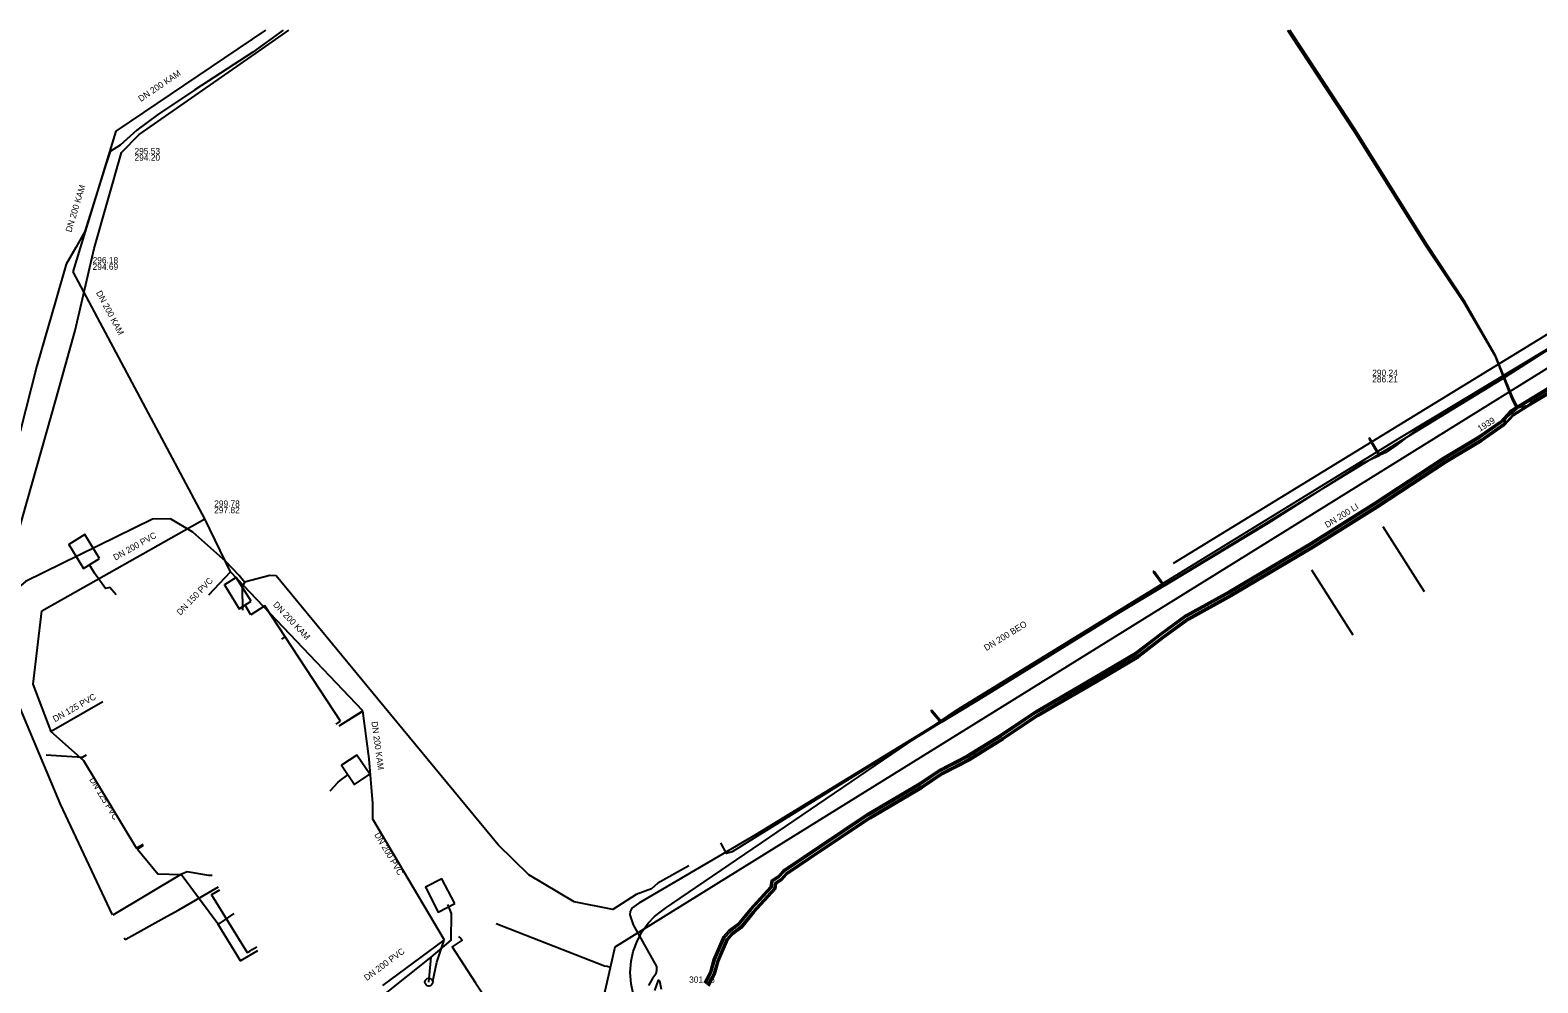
# Model space of a CAD drawing. Extents: x -600391 to -599491, y -1160176 to -1159402.
# Drawn here: x -599833.6 to -599641, y -1159523.5 to -1159401.8 of the extents above; entities that cross this region are included whole.
import ezdxf

# ---------------------------------------------------------------- set-up
doc = ezdxf.new("R2010")
doc.units = 0
for name, color, linetype in [('CETIN_linie', 7, 'Continuous'), ('FASTER_linie', 7, 'Continuous'), ('Vrstva 1', 7, 'Continuous'), ('Vrstva 12', 7, 'Continuous'), ('Vrstva 13', 7, 'Continuous'), ('Vrstva 15', 7, 'Continuous'), ('Vrstva 16', 7, 'Continuous'), ('Vrstva 3', 7, 'Continuous'), ('Vrstva 4', 7, 'Continuous'), ('Vrstva 42', 7, 'Continuous'), ('Vrstva 44', 7, 'Continuous'), ('Vrstva 5', 7, 'Continuous'), ('Vrstva 55', 7, 'Continuous'), ('Vrstva 58', 7, 'Continuous'), ('Vrstva 8', 7, 'Continuous'), ('Vrstva 9', 7, 'Continuous')]:
    doc.layers.add(name, color=color, linetype=linetype)

msp = doc.modelspace()

# ---------------------------------------------------------------- linework, layer by layer
at = {"layer": 'CETIN_linie'}
for points in [[(-599687.5, -1159469.87), (-599639.61, -1159440.54)], [(-599660.76, -1159465.2), (-599655.49, -1159473.49)], [(-599669.88, -1159470.73), (-599664.61, -1159479.02)]]:
    msp.add_lwpolyline(points, dxfattribs=at)
at = {"layer": 'FASTER_linie'}
for points in [[(-599806.85, -1159471.45), (-599808.57, -1159469.66), (-599812.78, -1159465.92), (-599815.61, -1159464.23), (-599817.92, -1159464.25), (-599834.16, -1159472.24), (-599835.99, -1159473.78), (-599837.27, -1159479.34), (-599839.09, -1159485.23)], [(-599806.16, -1159472.29), (-599806.85, -1159471.45)], [(-599806.16, -1159472.29), (-599806.47, -1159472.94), (-599806.42, -1159475.89)], [(-599749.42, -1159508.58), (-599753.39, -1159510.79), (-599754.19, -1159511.5), (-599756.16, -1159512.22), (-599759.12, -1159514.12), (-599764.08, -1159513.14), (-599769.86, -1159509.7), (-599773.76, -1159505.86), (-599789.14, -1159487.25), (-599802.11, -1159471.49), (-599802.92, -1159471.46), (-599806.16, -1159472.29)]]:
    msp.add_lwpolyline(points, dxfattribs=at)
at = {"layer": 'Vrstva 1'}
for p, q in [((-599825.34, -1159471.15), (-599825.96, -1159470.09)), ((-599805.38, -1159476.47), (-599806.08, -1159475.23)), ((-599801.41, -1159479.6), (-599800.97, -1159479.31)), ((-599829.66, -1159500.68), (-599835.73, -1159486.27)), ((-599794.45, -1159490.47), (-599793.92, -1159490.07)), ((-599793.95, -1159497.66), (-599792.96, -1159496.93)), ((-599823.03, -1159514.83), (-599829.66, -1159500.68)), ((-599814.3, -1159509.65), (-599823.01, -1159514.88)), ((-599809.6, -1159515.98), (-599814.26, -1159509.66)), ((-599779.72, -1159514.64), (-599780.21, -1159513.48)), ((-599782.63, -1159523.42), (-599782.34, -1159520.25))]:
    msp.add_line(p, q, dxfattribs=at)
for points in [[(-599658.59, -1159453.85), (-599624.47, -1159433.28), (-599582.91, -1159406.12), (-599577.31, -1159401.77)], [(-599756.17, -1159526.09), (-599756.54, -1159524.86), (-599756.77, -1159523.63), (-599756.9, -1159522.21), (-599756.8, -1159520.76), (-599756.51, -1159519.5), (-599755.99, -1159518.12), (-599755.38, -1159516.95), (-599754.61, -1159515.89), (-599753.8, -1159515.05), (-599752.93, -1159514.34), (-599752.22, -1159513.83), (-599751.58, -1159513.4), (-599715.24, -1159488.66), (-599658.59, -1159453.85)], [(-599822.58, -1159473.92), (-599823.39, -1159472.99), (-599823.91, -1159473.14), (-599825.34, -1159471.15)], [(-599793.92, -1159490.07), (-599800.97, -1159479.31), (-599803.56, -1159475.35), (-599805.38, -1159476.47)], [(-599826.42, -1159494.42), (-599826.9, -1159494.72), (-599831.53, -1159494.41)], [(-599795.25, -1159498.97), (-599794.27, -1159497.91), (-599793.95, -1159497.66)], [(-599819.1, -1159505.98), (-599819.86, -1159506.45), (-599817.23, -1159509.58), (-599814.3, -1159509.65)], [(-599810.3, -1159509.79), (-599810.72, -1159509.79), (-599813.52, -1159509.34), (-599814.3, -1159509.65)], [(-599807.55, -1159514.65), (-599809.44, -1159515.98), (-599809.6, -1159515.98)], [(-599788.42, -1159525.07), (-599782.34, -1159520.25), (-599779.79, -1159518.07), (-599779.72, -1159514.64)], [(-599804.52, -1159519.41), (-599806.67, -1159520.7), (-599809.6, -1159515.98)]]:
    msp.add_lwpolyline(points, dxfattribs=at)
at = {"layer": 'Vrstva 13'}
for points in [[(-599757.93, -1159531.49), (-599760.55, -1159526.41), (-599759.42, -1159521.54), (-599758.81, -1159518.92), (-599742.22, -1159508.61), (-599680.74, -1159470.43), (-599612.05, -1159427.77), (-599574.38, -1159404.36), (-599573.73, -1159403.97), (-599570.13, -1159401.77)], [(-599759.42, -1159521.54), (-599759.85, -1159521.44), (-599760.19, -1159521.36), (-599774.01, -1159515.97)], [(-599778.86, -1159517.59), (-599778.55, -1159517.83), (-599778.39, -1159518.06), (-599779.66, -1159518.93), (-599776.67, -1159523.51), (-599774.59, -1159526.64), (-599774.33, -1159527.11), (-599774.71, -1159529.11), (-599779.55, -1159532.55), (-599783.41, -1159534.94), (-599785.07, -1159534.35), (-599786.65, -1159535.02)]]:
    msp.add_lwpolyline(points, dxfattribs=at)
at = {"layer": 'Vrstva 16'}
for points in [[(-599821.54, -1159517.75), (-599821.41, -1159517.95), (-599821.33, -1159517.91), (-599816.06, -1159515), (-599814.55, -1159514.18), (-599809.51, -1159511.25)], [(-599809.36, -1159511.66), (-599810.4, -1159512.28), (-599805.85, -1159519.63), (-599805.5, -1159519.46), (-599805.19, -1159519.27), (-599804.58, -1159518.91)]]:
    msp.add_lwpolyline(points, dxfattribs=at)
at = {"layer": 'Vrstva 3'}
for points in [[(-599824.69, -1159469.3), (-599826.59, -1159466.24), (-599828.63, -1159467.51), (-599826.73, -1159470.56)], [(-599805.32, -1159474.75), (-599807.23, -1159471.7), (-599808.75, -1159472.66), (-599806.84, -1159475.71)], [(-599790.18, -1159496.86), (-599791.82, -1159494.4), (-599793.79, -1159495.7), (-599792.14, -1159498.15)], [(-599779.32, -1159513.37), (-599780.95, -1159510.2), (-599783.05, -1159511.29), (-599781.42, -1159514.46)]]:
    msp.add_lwpolyline(points, close=True, dxfattribs=at)
msp.add_circle((-599782.63, -1159523.42), 0.5, dxfattribs=at)
at = {"layer": 'Vrstva 42'}
msp.add_lwpolyline([(-599801.24, -1159401.77), (-599805.13, -1159404.58), (-599812.51, -1159409.39), (-599817.29, -1159412.61), (-599819.94, -1159414.55), (-599822.04, -1159416.45), (-599823.32, -1159417.28), (-599823.85, -1159418.81), (-599826.59, -1159427.49), (-599827.71, -1159429.53), (-599828.97, -1159431.67), (-599830.28, -1159436.28), (-599832.7, -1159444.66), (-599834.85, -1159453.07)], dxfattribs=at)
at = {"layer": 'Vrstva 44'}
msp.add_line((-599645.34, -1159452.22), (-599645.27, -1159452.03), dxfattribs=at)
for points in [[(-599672.95, -1159401.77), (-599672.48, -1159402.5), (-599664.44, -1159414.71), (-599655.35, -1159429.21), (-599650.41, -1159436.58), (-599646.45, -1159443.33), (-599644.27, -1159448.99), (-599643.67, -1159450.17), (-599644.48, -1159450.83), (-599645.06, -1159451.4)], [(-599642.34, -1159449.78), (-599643.14, -1159449.95), (-599643.47, -1159450.05), (-599644.12, -1159448.85), (-599646.44, -1159443.28), (-599650.32, -1159436.49), (-599655.18, -1159429.08), (-599664.27, -1159414.56), (-599672.25, -1159402.38), (-599672.65, -1159401.77)], [(-599642.34, -1159449.78), (-599641.85, -1159449.37), (-599639.44, -1159447.92), (-599635.45, -1159445.76), (-599629.36, -1159442.22), (-599625.21, -1159439.74), (-599616.06, -1159434.03), (-599605.74, -1159427.52), (-599597.76, -1159422.76), (-599590.03, -1159417.81), (-599584.48, -1159414.27), (-599580.6, -1159412.35), (-599575.82, -1159410.73), (-599571.95, -1159409.24), (-599569.31, -1159407.65), (-599567.26, -1159405.2), (-599564.84, -1159402.48), (-599564.3, -1159401.77)], [(-599746.86, -1159523.92), (-599746.06, -1159522.4), (-599745.59, -1159520.75), (-599744.4, -1159517.98), (-599743.82, -1159517.35), (-599742.67, -1159516.47), (-599741.07, -1159514.51), (-599738.32, -1159511.5), (-599738.21, -1159510.84), (-599737.55, -1159510.41), (-599736.89, -1159509.68), (-599732.29, -1159506.57), (-599726.22, -1159502.51), (-599719.59, -1159498.6), (-599716.92, -1159496.8), (-599713.54, -1159495.06), (-599709.23, -1159492.39), (-599704.74, -1159489.39), (-599697.19, -1159484.99), (-599691.93, -1159481.89), (-599688.73, -1159479.41), (-599685.52, -1159477.1), (-599680.07, -1159474.07), (-599669.63, -1159467.89), (-599661.47, -1159462.75), (-599652.65, -1159456.98), (-599648.09, -1159454.23), (-599645.28, -1159452.3), (-599644.06, -1159450.95), (-599642.3, -1159449.87), (-599639.34, -1159448.1)], [(-599645.34, -1159452.22), (-599644.12, -1159450.87), (-599642.34, -1159449.78)], [(-599747.02, -1159523.8), (-599746.24, -1159522.32), (-599745.77, -1159520.69), (-599744.57, -1159517.87), (-599743.96, -1159517.21), (-599742.81, -1159516.33), (-599741.23, -1159514.38), (-599738.5, -1159511.4), (-599738.39, -1159510.72), (-599737.69, -1159510.25), (-599737.03, -1159509.52), (-599732.41, -1159506.41), (-599726.32, -1159502.34), (-599719.69, -1159498.43), (-599717.02, -1159496.62), (-599713.64, -1159494.88), (-599709.33, -1159492.23), (-599704.84, -1159489.22), (-599697.29, -1159484.81), (-599692.05, -1159481.73), (-599688.85, -1159479.25), (-599685.62, -1159476.93), (-599680.17, -1159473.89), (-599669.73, -1159467.72), (-599661.57, -1159462.59), (-599652.75, -1159456.81), (-599648.19, -1159454.07), (-599645.4, -1159452.14), (-599645.27, -1159452.03), (-599645.06, -1159451.4)]]:
    msp.add_lwpolyline(points, dxfattribs=at)
at = {"layer": 'Vrstva 5'}
for p, q in [((-599832.05, -1159475.97), (-599811.24, -1159464.22)), ((-599807.97, -1159471.01), (-599811.24, -1159464.22)), ((-599810.73, -1159473.91), (-599807.97, -1159471.01)), ((-599810.73, -1159473.91), (-599807.97, -1159471.01)), ((-599791.08, -1159488.77), (-599807.97, -1159471.01)), ((-599833.16, -1159485.33), (-599832.05, -1159475.97)), ((-599830.89, -1159491.38), (-599833.16, -1159485.33)), ((-599824.25, -1159487.61), (-599830.89, -1159491.38)), ((-599824.25, -1159487.61), (-599830.89, -1159491.38)), ((-599794.07, -1159490.68), (-599791.08, -1159488.77)), ((-599794.07, -1159490.68), (-599791.07, -1159488.79)), ((-599780.64, -1159518.07), (-599789.78, -1159502.58)), ((-599788.51, -1159523.85), (-599780.67, -1159518.04))]:
    msp.add_line(p, q, dxfattribs=at)
for points in [[(-599789.78, -1159502.58), (-599789.78, -1159500.61), (-599790.25, -1159494.87), (-599791.08, -1159488.77)], [(-599819.11, -1159505.82), (-599819.95, -1159506.29), (-599826.7, -1159495.13), (-599830.94, -1159491.36)], [(-599819.11, -1159505.82), (-599819.95, -1159506.29), (-599826.7, -1159495.13), (-599830.94, -1159491.36)], [(-599782.11, -1159523.31), (-599781.6, -1159520.88), (-599780.67, -1159518.04)], [(-599782.11, -1159523.31), (-599781.6, -1159520.88), (-599780.67, -1159518.04)]]:
    msp.add_lwpolyline(points, dxfattribs=at)
at = {"layer": 'Vrstva 55'}
msp.add_lwpolyline([(-599638.23, -1159441.71), (-599646.11, -1159446.64), (-599656.61, -1159452.92), (-599659.04, -1159454.82), (-599660.38, -1159455.75), (-599661.14, -1159456.09), (-599662.43, -1159453.95), (-599662.53, -1159453.89), (-599662.53, -1159454.01), (-599661.24, -1159456.15), (-599663.43, -1159457.14), (-599675.45, -1159464.81), (-599685.34, -1159470.77), (-599688.66, -1159472.76), (-599689.95, -1159470.97), (-599690.06, -1159470.92), (-599690.05, -1159471.04), (-599688.76, -1159472.82), (-599694.57, -1159476.31), (-599711.7, -1159486.91), (-599717.12, -1159490.2), (-599718.35, -1159488.77), (-599718.46, -1159488.73), (-599718.44, -1159488.84), (-599717.22, -1159490.26), (-599728.49, -1159497.17), (-599743.9, -1159506.77), (-599744.61, -1159506.99), (-599745.33, -1159505.64)], dxfattribs=at)
at = {"layer": 'Vrstva 58'}
for points in [[(-599835.13, -1159466.19), (-599830.29, -1159449), (-599827.81, -1159440.14), (-599825.36, -1159429.68), (-599821.88, -1159417.42), (-599819.62, -1159415.11), (-599804.35, -1159404.46), (-599800.51, -1159401.77)], [(-599625.61, -1159433.62), (-599645.63, -1159446.41), (-599662.35, -1159456.63), (-599681.81, -1159468.53), (-599698.13, -1159478.4), (-599721.06, -1159492.47), (-599740.91, -1159504.58), (-599755.82, -1159513.34), (-599756.7, -1159513.97), (-599756.91, -1159514.38), (-599756.96, -1159514.82), (-599756.52, -1159516.08), (-599753.56, -1159521.42), (-599753.53, -1159521.94), (-599753.64, -1159522.39), (-599754.05, -1159522.95), (-599754.59, -1159523.86)], [(-599747.44, -1159523.53), (-599746.71, -1159522.14), (-599746.25, -1159520.52), (-599744.99, -1159517.6), (-599744.3, -1159516.84), (-599743.16, -1159515.97), (-599741.6, -1159514.05), (-599738.97, -1159511.18), (-599738.85, -1159510.42), (-599738.01, -1159509.87), (-599737.36, -1159509.14), (-599732.68, -1159505.99), (-599726.59, -1159501.91), (-599719.96, -1159498), (-599717.28, -1159496.19), (-599713.89, -1159494.45), (-599709.6, -1159491.81), (-599705.11, -1159488.79), (-599697.54, -1159484.38), (-599692.33, -1159481.31), (-599689.15, -1159478.85), (-599685.89, -1159476.5), (-599680.42, -1159473.46), (-599669.99, -1159467.29), (-599661.84, -1159462.17), (-599653.02, -1159456.38), (-599648.46, -1159453.65), (-599645.74, -1159451.77), (-599644.51, -1159450.4), (-599642.65, -1159449.27), (-599639.69, -1159447.49)], [(-599747.27, -1159523.64), (-599746.52, -1159522.21), (-599746.06, -1159520.59), (-599744.82, -1159517.71), (-599744.16, -1159516.98), (-599743.02, -1159516.11), (-599741.45, -1159514.18), (-599738.79, -1159511.27), (-599738.67, -1159510.54), (-599737.88, -1159510.02), (-599737.22, -1159509.3), (-599732.57, -1159506.16), (-599726.48, -1159502.08), (-599719.85, -1159498.17), (-599717.17, -1159496.37), (-599713.79, -1159494.62), (-599709.5, -1159491.97), (-599705, -1159488.96), (-599697.44, -1159484.56), (-599692.21, -1159481.48), (-599689.03, -1159479.01), (-599685.79, -1159476.67), (-599680.32, -1159473.63), (-599669.89, -1159467.46), (-599661.74, -1159462.33), (-599652.91, -1159456.55), (-599648.36, -1159453.81), (-599645.61, -1159451.92), (-599644.38, -1159450.56), (-599642.55, -1159449.44), (-599639.59, -1159447.66)], [(-599753.77, -1159524.51), (-599753.29, -1159523.16), (-599753.18, -1159523.24), (-599752.97, -1159524.31)]]:
    msp.add_lwpolyline(points, dxfattribs=at)
at = {"layer": 'Vrstva 9'}
for p, q in [((-599822.57, -1159414.67), (-599803.44, -1159401.77)), ((-599828.04, -1159432.66), (-599822.57, -1159414.67)), ((-599811.24, -1159464.22), (-599828.04, -1159432.66))]:
    msp.add_line(p, q, dxfattribs=at)

# ---------------------------------------------------------------- texts
at = {"layer": 'Vrstva 12'}
for rotation, p in [(33.9764, (-599819.41, -1159410.96)), (73.1094, (-599828.3, -1159427.66)), (298.0245, (-599825.17, -1159435.32))]:
    msp.add_text('DN 200 KAM', height=0.8, rotation=rotation, dxfattribs=at).set_placement(p)
for s, p in [('295.53', (-599820.23, -1159417.63)), ('294.20', (-599820.23, -1159418.46)), ('296.18', (-599825.58, -1159431.57)), ('294.69', (-599825.58, -1159432.4))]:
    msp.add_text(s, height=0.8, dxfattribs=at).set_placement(p)
at = {"layer": 'Vrstva 15'}
for s, p in [('1939', (-599648.37, -1159453.11)), ('DN 200 LI', (-599667.88, -1159465.41))]:
    msp.add_text(s, height=0.8, rotation=31.8565, dxfattribs=at).set_placement(p)
at = {"layer": 'Vrstva 4'}
for s, p in [('290.24', (-599662.13, -1159445.95)), ('286.21', (-599662.13, -1159446.78)), ('301.26', (-599749.38, -1159523.5))]:
    msp.add_text(s, height=0.8, dxfattribs=at).set_placement(p)
msp.add_text('DN 200 BEO', height=0.8, rotation=31.5669, dxfattribs=at).set_placement((-599711.42, -1159481.13))
at = {"layer": 'Vrstva 8'}
for s, p in [('299.78', (-599810.05, -1159462.67)), ('297.82', (-599810.05, -1159463.5))]:
    msp.add_text(s, height=0.8, dxfattribs=at).set_placement(p)
for s, rotation, p in [('DN 200 PVC', 29.4452, (-599822.66, -1159469.57)), ('DN 150 PVC', 46.4046, (-599814.36, -1159476.61)), ('DN 200 KAM', 313.5637, (-599802.59, -1159475.25)), ('DN 125 PVC', 29.5867, (-599830.38, -1159490.22)), ('DN 200 KAM', 277.7507, (-599789.97, -1159490.16)), ('DN 125 PVC', 301.1672, (-599826.03, -1159497.54)), ('DN 200 PVC', 300.5413, (-599789.63, -1159504.58)), ('DN 200 PVC', 36.5411, (-599790.55, -1159523.29))]:
    msp.add_text(s, height=0.8, rotation=rotation, dxfattribs=at).set_placement(p)

doc.saveas('drawing.dxf')
